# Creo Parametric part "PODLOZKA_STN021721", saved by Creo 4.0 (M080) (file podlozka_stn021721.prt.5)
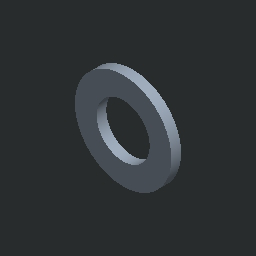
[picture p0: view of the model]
Units: Custom; MM, KILOGRAM, SECS
Materials in the file: OCEL, OCEL_N

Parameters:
  PTC_MATERIAL_NAME = "OCEL"
  NAZOV = "PODLOZKA_STN021721"
  NORMA = "STN 02 1721"

Other parameters: HMOTNOST, HUSTOTA

Layers: 1, 2, 3, 4, 5, 6, 7, 8, 9, 10, 11, 12, 13, 14, 15, 16, 17, 18, 19, 20, 21, 22, 23, 24, 25, 26, 27, 28, 29, 30, 31, 32

Family table entries: GENERIC, PODLOZKA_5, PODLOZKA_STN021721, value(d_val), 2/$, value(i_val), PODLOZKA_6, PODLOZKA_STN021721, 2/(, PODLOZKA_7, PODLOZKA_STN021721, 2/,, PODLOZKA_8, PODLOZKA_STN021721, !/", 2/0, PODLOZKA_10, PODLOZKA_STN021721, !/&, 2/4, PODLOZKA_12, PODLOZKA_STN021721, !/+, 2/8, PODLOZKA_14, PODLOZKA_STN021721, !//, 2/<, PODLOZKA_16, PODLOZKA_STN021721, 2/>, PODLOZKA_18, PODLOZKA_STN021721, !/4, 2/A, PODLOZKA_20, PODLOZKA_STN021721, !/6, PODLOZKA_22, PODLOZKA_STN021721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

Surfaces: 2 plane, 2 cylinder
